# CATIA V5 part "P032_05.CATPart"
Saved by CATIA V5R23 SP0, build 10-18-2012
Part number: 05-LICP-T02-E-S03-P032_05
Bounding box of the stored display mesh (mm): x 0.735 to 1.47, y -11.193 to 11.193, z -11.202 to 11.202
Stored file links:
  C:\wamp\www\COURS\CONCEPTION GMP1\TITRE 02-SEMESTRE 2\03-TP7-PRESSE MECANIQUE\eleve\P032_05.CATPart
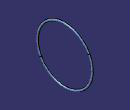
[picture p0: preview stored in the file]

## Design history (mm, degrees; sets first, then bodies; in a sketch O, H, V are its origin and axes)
Body1 (main body)
  Solid1: solid without history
